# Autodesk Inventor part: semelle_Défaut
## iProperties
Shininess: 64.0
Length Units: 11269
Angle Units: 11279
Time Units: 11290
Mass Units: 11283
Length Display Precision: 3
Angle Display Precision: 2
Compacted: True
Part Number: semelle_Défaut
Document SubType Name: Modeling
Created: 2006-11
Material: Par défaut
Designer: profs_sti
Density: 0.0
Volumn: 0.0
Area: 0.0
PropertySet Name: Model Information
Control State: 0
Master: False
Checked Out: False
Author: profs_sti
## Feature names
1. Base1
